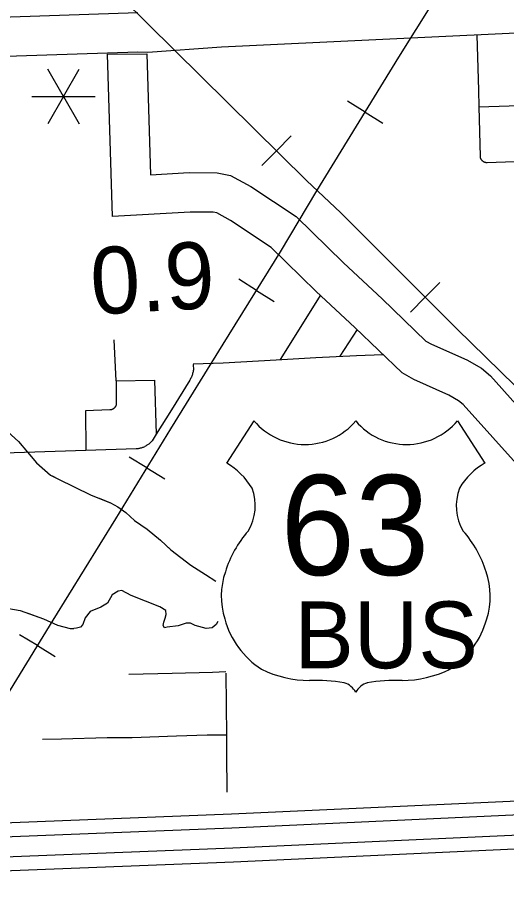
# Model space of a CAD drawing. Extents: x 309348 to 309445, y 336383 to 336484.
# Drawn here: x 309351.915 to 309352.534, y 336397.601 to 336398.714 of the extents above; entities that cross this region are included whole.
import ezdxf

# ---------------------------------------------------------------- set-up
doc = ezdxf.new("R2010")
doc.units = 0
doc.layers.add('R_Annotation', color=7, linetype='Continuous')

msp = doc.modelspace()

# ---------------------------------------------------------------- linework, layer by layer
at = {"layer": 'R_Annotation'}
for p, q in [((309351.9734, 336398.6141), (309351.9534, 336398.6488)), ((309351.9734, 336398.6141), (309351.9934, 336398.6488)), ((309351.9334, 336398.6141), (309351.9734, 336398.6141)), ((309351.9734, 336398.6141), (309351.9534, 336398.5795)), ((309351.9734, 336398.6141), (309352.0134, 336398.6141)), ((309351.9734, 336398.6141), (309351.9934, 336398.5795)), ((309352.3551, 336398.5944), (309352.3326, 336398.6082)), ((309352.3551, 336398.5944), (309352.3776, 336398.5806)), ((309352.2429, 336398.5455), (309352.2614, 336398.5642)), ((309352.2429, 336398.5455), (309352.2243, 336398.5267)), ((309352.2176, 336398.3689), (309352.1952, 336398.3829)), ((309352.431, 336398.3601), (309352.4497, 336398.3788)), ((309352.2176, 336398.3689), (309352.24, 336398.355)), ((309352.431, 336398.3601), (309352.4123, 336398.3415)), ((309352.2144, 336398.2039), (309352.1798, 336398.1504)), ((309352.4719, 336398.2039), (309352.5065, 336398.1504)), ((309352.079, 336398.1442), (309352.0565, 336398.1579)), ((309352.079, 336398.1442), (309352.1015, 336398.1304)), ((309351.9404, 336397.9194), (309351.9178, 336397.9331)), ((309351.9404, 336397.9194), (309351.9629, 336397.9056))]:
    msp.add_line(p, q, dxfattribs=at)
for points in [[(309351.8019, 336397.6945), (309351.8348, 336397.7477), (309351.8936, 336397.8428), (309351.9602, 336397.9518), (309352.0396, 336398.0797), (309352.1092, 336398.1936), (309352.1753, 336398.3008), (309352.248, 336398.4178), (309352.294, 336398.4947), (309352.3976, 336398.6638), (309352.4636, 336398.7692)], [(309351.8019, 336397.6945), (309351.8348, 336397.7477), (309351.8936, 336397.8428), (309351.9602, 336397.9518), (309352.0396, 336398.0797), (309352.1092, 336398.1936), (309352.1753, 336398.3008), (309352.248, 336398.4178), (309352.294, 336398.4947), (309352.3976, 336398.6638), (309352.4636, 336398.7692)], [(309352.563, 336398.2306), (309352.4709, 336398.3202), (309352.4079, 336398.3833), (309352.3237, 336398.4675), (309352.2813, 336398.5075), (309352.0135, 336398.7722)], [(309352.563, 336398.2306), (309352.4709, 336398.3202), (309352.4079, 336398.3833), (309352.3237, 336398.4675), (309352.2813, 336398.5075), (309352.0135, 336398.7722)], [(309352.5905, 336398.6964), (309352.1735, 336398.6764), (309352.0801, 336398.67), (309352.0674, 336398.6704), (309351.7217, 336398.6587), (309351.6685, 336398.6567), (309351.6665, 336398.7067), (309351.7199, 336398.7087), (309352.0674, 336398.7204)], [(309352.4963, 336398.6919), (309352.4985, 336398.6223), (309352.499, 336398.6009)], [(309352.5543, 336398.1411), (309352.4789, 336398.2246), (309352.4732, 336398.2293), (309352.461, 336398.2365), (309352.4167, 336398.256), (309352.4018, 336398.2644), (309352.342, 336398.3219), (309352.293, 336398.3674), (309352.236, 336398.4233), (309352.1846, 336398.4574), (309352.1675, 336398.4668), (309352.1628, 336398.4677), (309352.1336, 336398.4679), (309352.0353, 336398.4622), (309352.0289, 336398.6679), (309352.0789, 336398.6683), (309352.0837, 336398.5151), (309352.1324, 336398.5179), (309352.168, 336398.5177), (309352.1848, 336398.5143), (309352.2105, 336398.5003), (309352.2676, 336398.4623), (309352.3276, 336398.4036), (309352.3767, 336398.358), (309352.4319, 336398.3048), (309352.4391, 336398.3007), (309352.4839, 336398.2811), (309352.5021, 336398.2703), (309352.5138, 336398.2606), (309352.5848, 336398.1811)], [(309352.499, 336398.6009), (309352.5887, 336398.6039)], [(309352.499, 336398.6009), (309352.5004, 336398.5382), (309352.5004, 336398.5379), (309352.5005, 336398.5376), (309352.5006, 336398.5373), (309352.5006, 336398.537), (309352.5007, 336398.5367), (309352.5008, 336398.5364), (309352.5009, 336398.5361), (309352.5011, 336398.5358), (309352.5012, 336398.5356), (309352.5013, 336398.5353), (309352.5015, 336398.535), (309352.5016, 336398.5348), (309352.5018, 336398.5345), (309352.502, 336398.5343), (309352.5022, 336398.5341), (309352.5024, 336398.5338), (309352.5026, 336398.5336), (309352.5028, 336398.5334), (309352.503, 336398.5332), (309352.5032, 336398.533), (309352.5034, 336398.5328)], [(309352.5034, 336398.5328), (309352.5037, 336398.5326), (309352.5039, 336398.5324), (309352.5042, 336398.5322), (309352.5044, 336398.5321), (309352.5047, 336398.5319), (309352.5049, 336398.5318), (309352.5052, 336398.5316), (309352.5055, 336398.5315), (309352.5057, 336398.5314), (309352.506, 336398.5313), (309352.5063, 336398.5312), (309352.5066, 336398.5311), (309352.5069, 336398.531), (309352.5072, 336398.531), (309352.5075, 336398.5309), (309352.5078, 336398.5308), (309352.5081, 336398.5308), (309352.5084, 336398.5308), (309352.5087, 336398.5308), (309352.509, 336398.5308), (309352.5093, 336398.5308), (309352.5905, 336398.5335)], [(309352.2983, 336398.3625), (309352.2739, 336398.3233), (309352.2477, 336398.2814)], [(309352.3448, 336398.3193), (309352.3229, 336398.2855)], [(309352.0399, 336398.2543), (309352.0377, 336398.3062)], [(309352.1375, 336398.276), (309352.1753, 336398.2773), (309352.2425, 336398.2811), (309352.2925, 336398.284), (309352.344, 336398.2866), (309352.3774, 336398.2879)], [(309352.1375, 336398.2751), (309352.1377, 336398.2684), (309352.1376, 336398.2672), (309352.1374, 336398.266), (309352.1371, 336398.2649), (309352.1368, 336398.2637), (309352.1365, 336398.2626), (309352.1361, 336398.2615), (309352.1357, 336398.2604), (309352.1353, 336398.2593), (309352.1348, 336398.2582), (309352.1343, 336398.2572), (309352.1338, 336398.2561), (309352.1332, 336398.2551), (309352.1101, 336398.2177), (309352.0908, 336398.1868)], [(309352.0399, 336398.2543), (309352.0402, 336398.2259), (309352.0402, 336398.2256), (309352.0402, 336398.2254), (309352.0401, 336398.2251), (309352.0401, 336398.2248), (309352.0401, 336398.2245), (309352.04, 336398.2242), (309352.0399, 336398.224), (309352.0399, 336398.2237), (309352.0398, 336398.2234), (309352.0397, 336398.2231), (309352.0396, 336398.2229), (309352.0395, 336398.2226), (309352.0394, 336398.2224), (309352.0392, 336398.2221), (309352.0391, 336398.2218), (309352.039, 336398.2216), (309352.0388, 336398.2214), (309352.0387, 336398.2211), (309352.0385, 336398.2209), (309352.0383, 336398.2207), (309352.0381, 336398.2205), (309352.0379, 336398.2202), (309352.0377, 336398.22), (309352.0375, 336398.2198), (309352.0373, 336398.2197), (309352.0371, 336398.2195), (309352.0369, 336398.2193), (309352.0367, 336398.2191), (309352.0364, 336398.219), (309352.0362, 336398.2188), (309352.0359, 336398.2187), (309352.0357, 336398.2185), (309352.0354, 336398.2184), (309352.0352, 336398.2183), (309352.0349, 336398.2182), (309352.0347, 336398.2181), (309352.0344, 336398.218), (309352.0341, 336398.2179), (309352.0338, 336398.2179), (309352.0336, 336398.2178), (309352.0333, 336398.2177), (309352.033, 336398.2177), (309352.0327, 336398.2177), (309352.0324, 336398.2176), (309352.0322, 336398.2176), (309352.0011, 336398.2167)], [(309352.0399, 336398.2543), (309352.0885, 336398.2554)], [(309352.0885, 336398.2554), (309352.0908, 336398.1868)], [(309351.8684, 336398.2195), (309351.8824, 336398.2065), (309351.9028, 336398.1898), (309351.9166, 336398.1776), (309351.9393, 336398.1506), (309351.957, 336398.1352), (309351.9671, 336398.1301), (309351.987, 336398.1203), (309352.0085, 336398.11), (309352.0327, 336398.1), (309352.042, 336398.0951), (309352.0522, 336398.088), (309352.0634, 336398.0777), (309352.0792, 336398.0669), (309352.0963, 336398.0527), (309352.1093, 336398.0405), (309352.1344, 336398.0212), (309352.1531, 336398.0095), (309352.1662, 336398.0011)], [(309352.0011, 336398.2167), (309352.0016, 336398.1667)], [(309352.0908, 336398.1868), (309352.0856, 336398.1785), (309352.0849, 336398.1778), (309352.0843, 336398.1771), (309352.0836, 336398.1764), (309352.0829, 336398.1758), (309352.0821, 336398.1751), (309352.0814, 336398.1745), (309352.0806, 336398.1739), (309352.0798, 336398.1734), (309352.079, 336398.1729), (309352.0782, 336398.1724), (309352.0773, 336398.1719), (309352.0765, 336398.1715)], [(309351.8462, 336398.1615), (309352.0016, 336398.1667)], [(309352.0016, 336398.1667), (309352.0653, 336398.1687), (309352.0663, 336398.1688), (309352.0673, 336398.1689), (309352.0682, 336398.169), (309352.0692, 336398.1691), (309352.0701, 336398.1693), (309352.071, 336398.1695), (309352.072, 336398.1698), (309352.0729, 336398.1701), (309352.0738, 336398.1704), (309352.0747, 336398.1707), (309352.0756, 336398.1711), (309352.0765, 336398.1715)], [(309351.9304, 336398.1612), (309351.9393, 336398.1506), (309351.957, 336398.1352), (309351.959, 336398.1341)], [(309351.959, 336398.1341), (309351.9671, 336398.1301), (309351.987, 336398.1203), (309351.9946, 336398.1167)], [(309352.0187, 336398.1058), (309352.0327, 336398.1), (309352.042, 336398.0951), (309352.0522, 336398.088), (309352.0634, 336398.0777), (309352.0792, 336398.0669), (309352.0844, 336398.0626)], [(309352.1042, 336398.0452), (309352.1093, 336398.0405), (309352.1344, 336398.0212), (309352.1531, 336398.0095), (309352.1662, 336398.0011)], [(309352.1685, 336397.95), (309352.1664, 336397.9463), (309352.1616, 336397.9419), (309352.1539, 336397.9409), (309352.14, 336397.945), (309352.1342, 336397.9477), (309352.1288, 336397.9477), (309352.1187, 336397.9443), (309352.1044, 336397.943), (309352.1014, 336397.9419), (309352.0997, 336397.9447), (309352.1004, 336397.9491), (309352.1021, 336397.9541), (309352.1034, 336397.9589), (309352.1027, 336397.964), (309352.0953, 336397.9687), (309352.0591, 336397.9829), (309352.0472, 336397.989), (309352.0425, 336397.9883), (309352.035, 336397.9836), (309352.0293, 336397.9731), (309352.0205, 336397.968), (309352.0073, 336397.9626), (309352.0008, 336397.9545), (309351.9978, 336397.9463), (309351.9948, 336397.943), (309351.99, 336397.9416), (309351.9864, 336397.9411)], [(309351.8947, 336397.968), (309351.9186, 336397.9639), (309351.948, 336397.9534), (309351.9657, 336397.9454), (309351.9819, 336397.9413), (309351.9864, 336397.9411)], [(309351.9284, 336397.9604), (309351.948, 336397.9534), (309351.9657, 336397.9454), (309351.9819, 336397.9413), (309351.9864, 336397.9411)], [(309352.1788, 336397.8862), (309352.1619, 336397.8856), (309352.111, 336397.8843), (309352.056, 336397.883)], [(309352.1788, 336397.8844), (309352.1795, 336397.8052)], [(309352.1795, 336397.8062), (309352.1552, 336397.8062), (309352.1165, 336397.8049), (309352.0605, 336397.8027), (309352.0285, 336397.8027), (309351.9709, 336397.8011), (309351.9469, 336397.8008)], [(309352.1795, 336397.8052), (309352.1798, 336397.7835)], [(309352.1798, 336397.7835), (309352.1802, 336397.7339)], [(309352.6868, 336397.729), (309352.1859, 336397.7061), (309351.1163, 336397.6639), (309350.5792, 336397.645), (309349.6821, 336397.6116), (309349.5744, 336397.6063), (309349.1696, 336397.5933), (309349.0937, 336397.5896), (309348.838, 336397.5802), (309348.6889, 336397.576), (309348.5061, 336397.574), (309348.4455, 336397.5778), (309348.4023, 336397.5837), (309348.3471, 336397.5936), (309348.2597, 336397.6131), (309348.2175, 336397.6264), (309348.1904, 336397.6364), (309348.1261, 336397.6629)], [(309348.1138, 336397.6496), (309348.1842, 336397.6206), (309348.212, 336397.6103), (309348.2553, 336397.5967), (309348.3438, 336397.5769), (309348.3996, 336397.567), (309348.4438, 336397.5608), (309348.5057, 336397.557), (309348.6892, 336397.559), (309348.8386, 336397.5632), (309349.0944, 336397.5726), (309349.1703, 336397.5763), (309349.5751, 336397.5893), (309349.6829, 336397.5946), (309350.5798, 336397.6281), (309351.1169, 336397.6469), (309352.1866, 336397.6891), (309352.6878, 336397.712)], [(309352.6892, 336397.6861), (309352.1877, 336397.6631), (309351.1179, 336397.6209), (309350.5807, 336397.6021), (309349.684, 336397.5686), (309349.5761, 336397.5633), (309349.1714, 336397.5504), (309349.0955, 336397.5466), (309348.8394, 336397.5372), (309348.6897, 336397.533), (309348.505, 336397.5309), (309348.4412, 336397.5349), (309348.3955, 336397.5413), (309348.3387, 336397.5514), (309348.2486, 336397.5715), (309348.2036, 336397.5857), (309348.1748, 336397.5963), (309348.0954, 336397.6291)], [(309348.0833, 336397.616), (309348.0912, 336397.6124), (309348.1686, 336397.5805), (309348.1981, 336397.5696), (309348.2442, 336397.5551), (309348.3353, 336397.5348), (309348.3929, 336397.5245), (309348.4395, 336397.518), (309348.5046, 336397.5139), (309348.69, 336397.516), (309348.8399, 336397.5202), (309349.0962, 336397.5296), (309349.1721, 336397.5334), (309349.5768, 336397.5463), (309349.6847, 336397.5516), (309350.5813, 336397.5851), (309351.1185, 336397.604), (309352.1884, 336397.6461), (309352.6902, 336397.6691)]]:
    msp.add_lwpolyline(points, dxfattribs=at)
for centre, radius, start, end in [((309352.2789, 336398.2582), 0.0843, 220.075, 319.6701), ((309352.4074, 336398.2582), 0.0843, 220.3299, 319.925), ((309352.1346, 336398.0726), 0.09, 30.7809, 59.7992), ((309352.5518, 336398.0726), 0.09, 120.0117, 149.2191), ((309352.1544, 336398.0963), 0.0617, 328.8105, 21.2108), ((309352.532, 336398.0963), 0.0617, 158.7892, 211.1895), ((309352.3156, 336397.9699), 0.1439, 138.9565, 162.6913), ((309352.3707, 336397.9699), 0.1439, 17.3087, 41.0435), ((309352.2681, 336397.9817), 0.0951, 160.9576, 197.3819), ((309352.4182, 336397.9817), 0.0951, 342.6181, 19.0424), ((309352.2836, 336397.982), 0.11, 195.1074, 237.1312), ((309352.4027, 336397.982), 0.11, 302.8688, 344.8926), ((309352.2857, 336398.0166), 0.1413, 244.0771, 269.5779), ((309352.4007, 336398.0166), 0.1413, 270.4221, 295.9229), ((309352.2889, 336397.6167), 0.2588, 81.1942, 90.9539), ((309352.3974, 336397.6167), 0.2588, 89.0461, 98.8058), ((309352.3213, 336397.8487), 0.0248, 28.0342, 72.9864), ((309352.3651, 336397.8487), 0.0248, 107.0136, 151.9658)]:
    msp.add_arc(centre, radius, start, end, dxfattribs=at)

# ---------------------------------------------------------------- texts
msp.add_text('0.9', height=0.08451, rotation=3.2985, dxfattribs=at).set_placement((309352.0099, 336398.338))
for s, height, p in [('63', 0.12664, (309352.2479, 336398.0087)), ('BUS', 0.08451, (309352.2654, 336397.8908))]:
    msp.add_text(s, height=height, dxfattribs=at).set_placement(p)

doc.saveas('drawing.dxf')
